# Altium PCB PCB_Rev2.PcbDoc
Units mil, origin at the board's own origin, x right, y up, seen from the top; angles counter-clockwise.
Board outline 1535 x 1720 mil, 2 copper layers (Top Layer, Bottom Layer), stack 61.2 mil thick; 17 components, 24 nets, 115 pads, 26 vias.
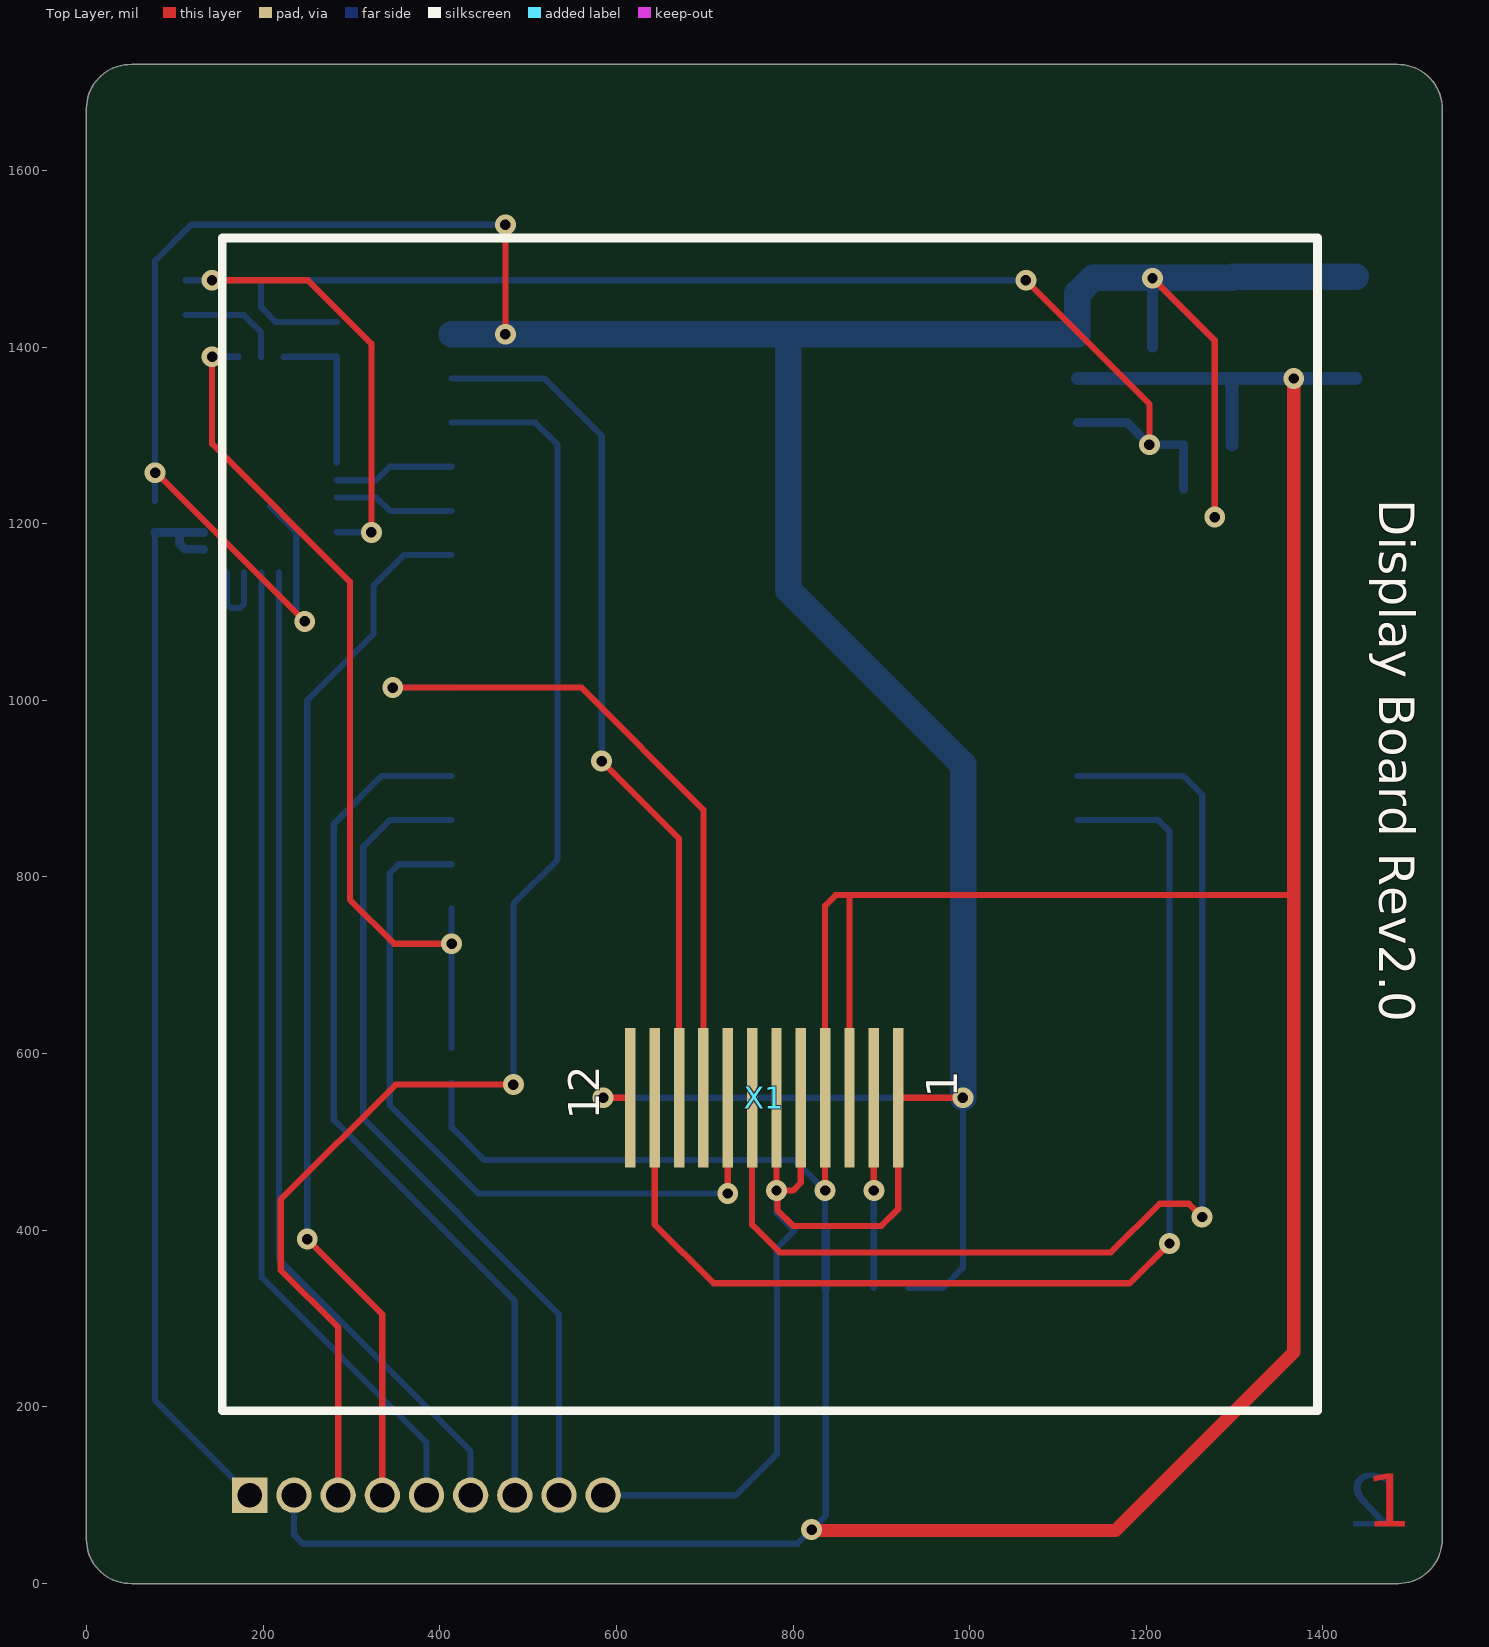
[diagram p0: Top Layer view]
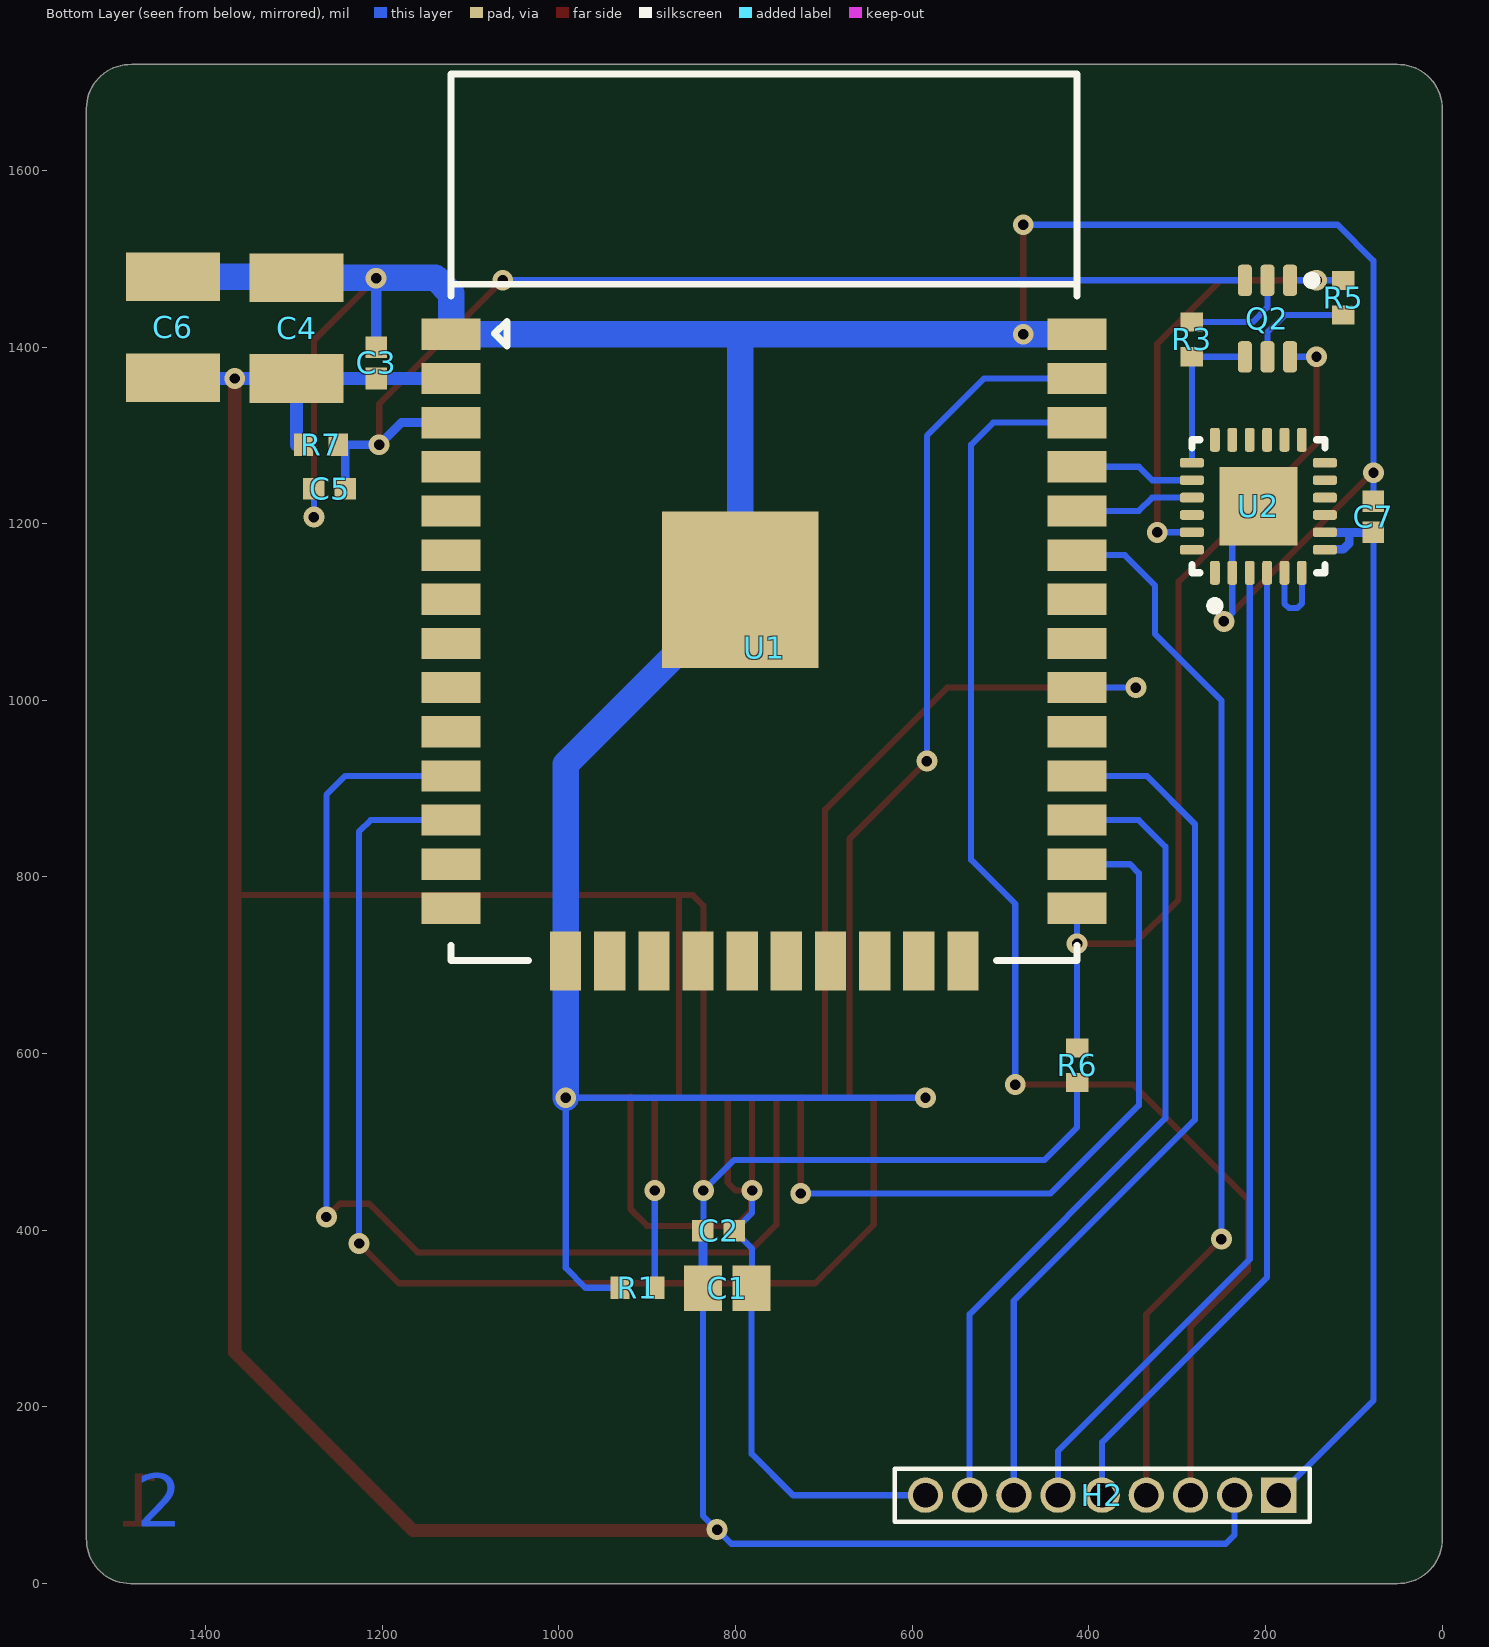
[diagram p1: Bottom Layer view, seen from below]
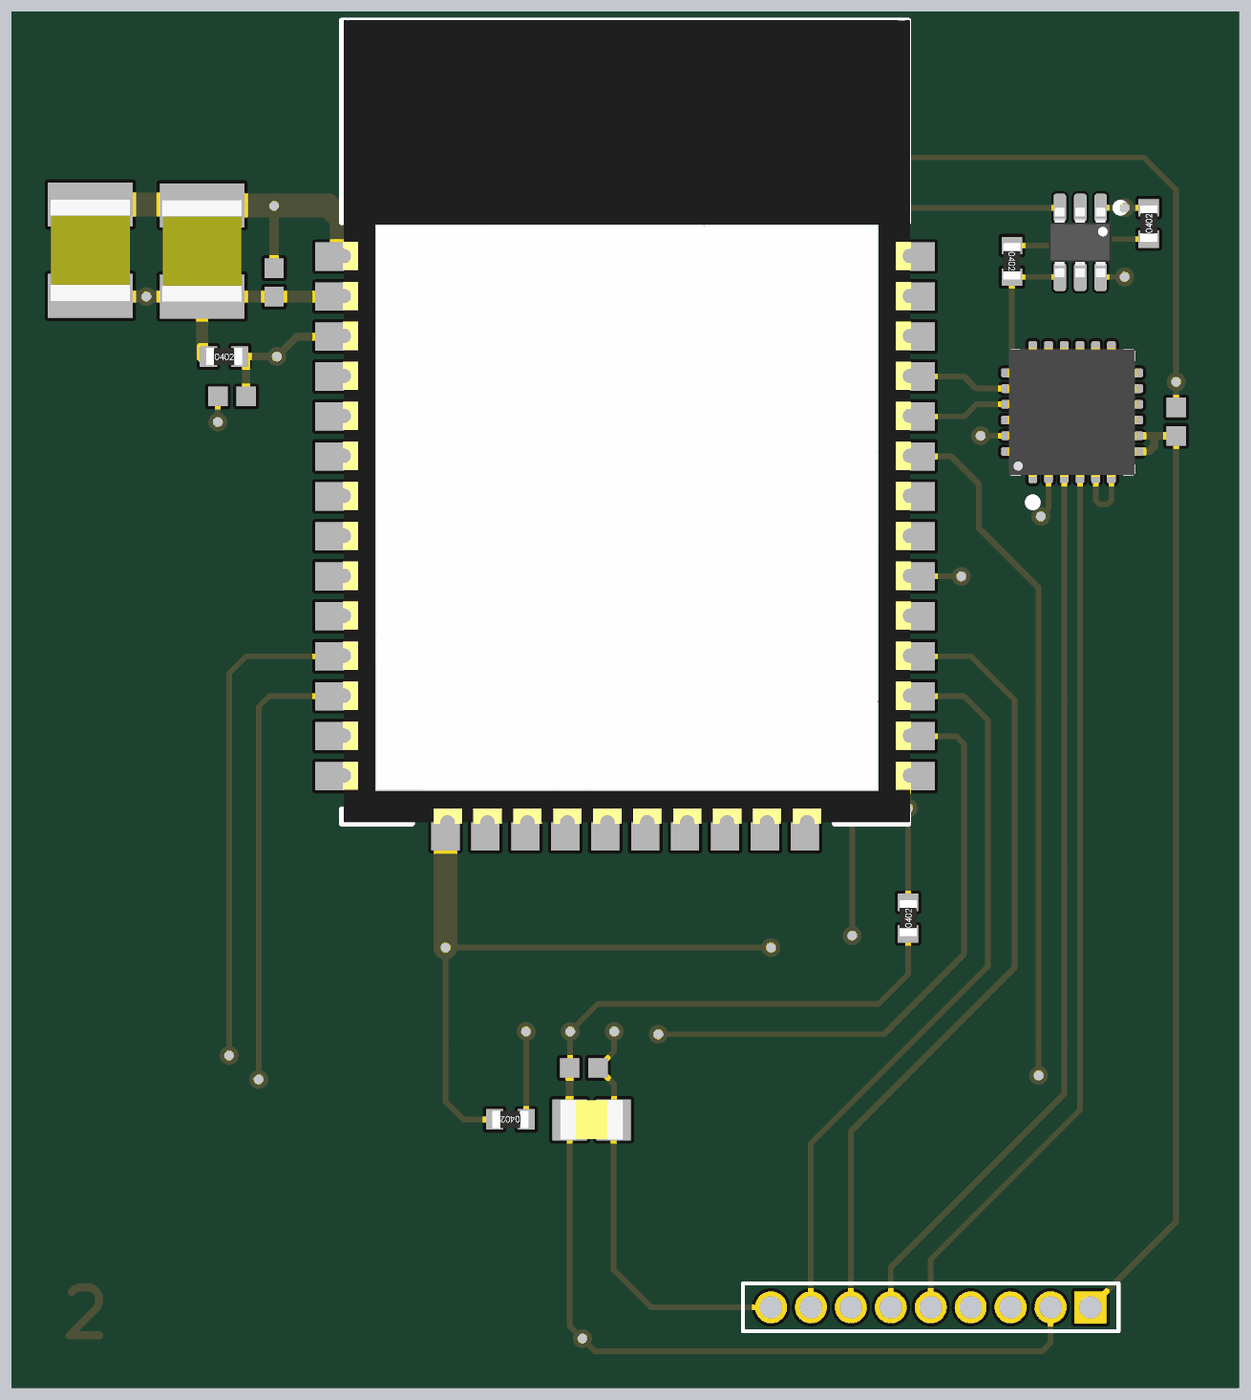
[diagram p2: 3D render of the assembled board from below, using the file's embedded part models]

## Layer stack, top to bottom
Top Solder: solder mask 0.4, Solder Resist, Dk 3.5
Top Layer: signal copper 1.4
Dielectric 1: dielectric 58.4, FR-4, Dk 4.8
Bottom Layer: signal copper 1.4
Bottom Solder: solder mask 0.4, Solder Resist, Dk 3.5

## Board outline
0,50 0,1670 cw(c50,1670) 51.04,1719.99 51.04,1720 1483.96,1720 1483.96,1719.99 cw(c1485,1670) 1535,1670 1535,51.04 1534.99,51.04 cw(c1485,50) 1485,0 51.04,0 51.04,0.01 cw(c50,50)

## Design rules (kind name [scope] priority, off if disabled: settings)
Clearance Clearance_U2 [All vs InComponent('U2')] p1: gap=6 ignorepadtopadclearanceinfootprint=FALSE
Clearance Clearance_Q2 [All vs InComponent('Q2')] p2: gap=6 ignorepadtopadclearanceinfootprint=FALSE
Clearance [All] p3: gap=10 ignorepadtopadclearanceinfootprint=FALSE except(0: Arc-Hole Track-Hole SMDPad-Hole THPad-Hole Via-Hole Fill-Hole Poly-Hole Region-Hole Text-Hole)
MinimumSolderMaskSliver [All] p1: minsoldermaskwidth=0.5
PolygonConnect [All] p1: connectstyle=Relief reliefconductorwidth=10 reliefentries=4 polygonreliefangle="90 Angle" airgapwidth=10
RoutingVias [All] p1: holewidth=28 width=50 viastyle="Through Hole" minholewidth=28 minwidth=50 maxholewidth=28 maxwidth=50
SilkToSilkClearance [All] p1: silktosilkclearance=5
SilkToSolderMaskClearance [IsPad] p1: minsilkscreentomaskgap=5 clearancetoexposedcopper=TRUE
SolderMaskExpansion [All] p1: expansion=4 istentingtop=FALSE
Width [All] p1: maxlimit=30 minlimit=7 preferedwidth=7
27 further rules are at their usual default settings.

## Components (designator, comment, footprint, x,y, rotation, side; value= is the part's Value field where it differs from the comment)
C1 "10uF" CAPC2012X140N 809.47,334.45 r180 bottom
C2 "0.1uF" CAPC1005X56N 819.31,399.45 r180 bottom
C3 "0.1uF" CAPC1005X56N 1207.03,1382.17 r90 bottom
C4 "47uF" CAPC3225X160N 1297.03,1421.54 r90 bottom
C5 "0.1uF" CAPC1005X56N 1259.74,1239.45 r0 bottom
C6 "47uF" CAPC3225X160N 1437.03,1422.36 r90 bottom
C7 "1uF" CAPC1005X56N 77.78,1207.95 r90 bottom
H2 "CON9" HDR9X1-50MIL 585,100 r270 bottom
Q2 "BC847S" SOT65P210X110-6N 198.76,1432.28 r270 bottom
R1 "22R" "RESC1005X40L (0402 FOOTPRINT)" 911.2,335 r0 bottom
R3 "10K" "RESC1005X40L (0402 FOOTPRINT)" 283.37,1408.66 r270 bottom
R5 "10K" "RESC1005X40L (0402 FOOTPRINT)" 112.18,1455.91 r90 bottom
R6 "10K" "RESC1005X40L (0402 FOOTPRINT)" 413.37,586.89 r90 bottom
R7 "10K" "RESC1005X40L (0402 FOOTPRINT)" 1269.59,1289.45 r180 bottom
U1 "ESP32" ESP32 789.7,1127.72 r180 bottom locked
U2 "CP2104N" 24-QFN 208.07,1219.76 r90 bottom locked
X1 "TFT_1.54\"" "TFT_GLASS 1.54 INCH" 767.5,550 r90 top locked

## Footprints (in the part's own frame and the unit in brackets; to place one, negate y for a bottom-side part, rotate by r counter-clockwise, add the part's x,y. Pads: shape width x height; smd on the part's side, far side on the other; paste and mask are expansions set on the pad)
24-QFN [mm] "24-QFN Exposed Pad (4x4)"
  rrect50% 0.69x0.28 smd: 1(-1.912,1.25) 2(-1.912,0.75) 3(-1.912,0.25) 4(-1.912,-0.25) 5(-1.912,-0.75) 6(-1.912,-1.25) 13(1.913,-1.25) 14(1.913,-0.75) 15(1.913,-0.25) 16(1.913,0.25) 17(1.913,0.75) 18(1.913,1.25)
  rrect50% 0.28x0.69 smd: 7(-1.25,-1.913) 8(-0.75,-1.913) 9(-0.25,-1.913) 10(0.25,-1.913) 11(0.75,-1.913) 12(1.25,-1.913) 19(1.25,1.913) 20(0.75,1.913) 21(0.25,1.913) 22(-0.25,1.913) 23(-0.75,1.913) 24(-1.25,1.913)
  rect 2.25x2.25 smd paste-1.3: 25(0,0)
  silkscreen extent -2.99,-1.91 1.91,1.91, body extent -2.05,-2.04 2.05,2.06, height 1.08
CAPC1005X56N [mm] "Chip Capacitor, 2-Leads, Body 1.0x0.5mm, IPC Medium Density (0402 ceramic)"
  rect 0.62x0.62 smd: 1(-0.45,0) 2(0.45,0)
  body extent -0.55,-0.3 0.55,0.3, height 0.6
CAPC2012X140N [mm] "Chip Capacitor, 2-Leads, Body 2.0x1.3mm, IPC Medium Density (0805 ceramic)"
  rect 1.1x1.3 smd: 1(-0.7,0) 2(0.7,0)
  body extent -1,-0.62 1,0.63, height 1.24
CAPC3225X160N [mm] "Chip Capacitor, 2-Leads, Body 3.2x2.5mm, IPC Medium Density, (1210)"
  rect 1.4x2.7 smd: 1(-1.45,0) 2(1.45,0)
  body extent -1.61,-1.26 1.61,1.26, height 0.62
ESP32 [mm]
  rect 1.7x0.9 smd: 1(-8.441,7.283) 2(-8.441,6.013) 3(-8.441,4.743) 4(-8.441,3.473) 5(-8.441,2.203) 6(-8.441,0.933) 7(-8.441,-0.337) 8(-8.441,-1.607) 9(-8.441,-2.877) 10(-8.441,-4.147) 11(-8.441,-5.417) 12(-8.441,-6.687) 13(-8.441,-7.957) 14(-8.441,-9.227) 25(9.559,-9.227) 26(9.559,-7.957) 27(9.559,-6.687) 28(9.559,-5.417) 29(9.559,-4.147) 30(9.559,-2.877) 31(9.559,-1.607) 32(9.559,-0.337) 33(9.559,0.933) 34(9.559,2.203) 35(9.559,3.473) 36(9.559,4.743) 37(9.559,6.013) 38(9.559,7.283)
  rect 0.9x1.7 smd: 15(-5.151,-10.737) 16(-3.881,-10.737) 17(-2.611,-10.737) 18(-1.341,-10.737) 19(-0.071,-10.737) 20(1.199,-10.737) 21(2.469,-10.737) 22(3.739,-10.737) 23(5.009,-10.737) 24(6.279,-10.737)
  rect 4.5x4.5 smd: 39(-0.121,-0.057)
  silkscreen extent -8.44,-10.73 9.56,14.77, body extent -8.42,-10.74 9.65,14.8, height 3.13
HDR9X1-50MIL [mil]
  rect 40x40 hole 28: 1(0,400)
  round 40 hole 28: 2(0,350) 3(0,300) 4(0,250) 5(0,200) 6(0,150) 7(0,100) 8(0,50) 9(0,0)
  silkscreen extent -30,-35 30,435
"RESC1005X40L (0402 FOOTPRINT)" [mm] "Chip Resistor, 2-Leads, Body 1.0x0.5mm, IPC Medium Density (0402)"
  rect 0.55x0.65 smd: 1(-0.5,0) 2(0.5,0)
  body extent -0.57,-0.27 0.58,0.28, height 0.41
SOT65P210X110-6N [mm] "SC70, 6-Leads, Body 2.4x2.2mm (max), Pitch 0.65mm, IPC Medium Density"
  rrect50% 0.9x0.4 smd mask+0.076: 1(-1.1,0.675) 2(-1.1,0.025) 3(-1.1,-0.625) 4(1.1,-0.625) 5(1.1,0.025) 6(1.1,0.675)
  silkscreen extent -1.22,1.18 -0.98,1.42, body extent -1.1,-0.97 1.1,1.01, height 0.99
"TFT_GLASS 1.54 INCH" [mm] "TFT_GLASS 1.54 INCH"
  rect 4x0.3 smd: 1(0,-3.85) 2(0,-3.15) 3(0,-2.45) 4(0,-1.75) 5(0,-1.05) 6(0,-0.35) 7(0,0.35) 8(0,1.05) 9(0,1.75) 10(0,2.45) 11(0,3.15) 12(0,3.85)
  Top Layer lines w0.254: 0,-3.85 0,-3.85
  silkscreen extent -9,-15.91 24.73,15.59, body extent -9,-15.91 24.73,15.59, height 2

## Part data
C1: library part CAP_0805, "CAP 10uF 0805", LCSC_Part_Number=C307520, Manufacturer=Samsung
C2: library part CAP_0402, "CAP 0.1uF 0402", LCSC_Part_Number=C344190, Manufacturer=CCTC
C3 C5: library part CAP_0402, "CAP 0.1uF 0402", Manufacturer=Yageo, PartNumber=C60474
C4 C6: library part CAP_1210, "CAP 47uF 1210"
C7: library part CAP_0603, "CAP 1uF 16V 0402", LCSC_Part_Number=C83063, Manufacturer=Walsin
H2: "CONN HEADER 9POS .100\" PADS", PartNumber=PADS
Q2: "TRANS 2NPN 44V 0.1A SC-70-6", LCSC_Part_Number=C148112, Manufacturer=Changjiang
R1: library part RES_0402, "RES 22R 0402", LCSC_Part_Number=C25092, Manufacturer=Uniroyal
R3 R5 R6 R7: library part RES_0402, "RES 10K 0402", LCSC_Part_Number=C258091, Manufacturer=Guangdong
U1: "WIFI/Bluetooth, SMD Module", Manufacturer=Ai-Thinker
U2: "IC BRIDGE USB TO UART 24QFN", LCSC_Part_Number=C47742, Manufacturer="Silicon Labs"
X1: library part "TFT_GLASS 1.54 INCH COLOR", "1.54 INCH TFT GLASS COLOR", Manufacturer=BuyDisplay

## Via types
v1: diameter 23.62, hole 11.81, Top Layer to Bottom Layer, tented both sides, 26 vias

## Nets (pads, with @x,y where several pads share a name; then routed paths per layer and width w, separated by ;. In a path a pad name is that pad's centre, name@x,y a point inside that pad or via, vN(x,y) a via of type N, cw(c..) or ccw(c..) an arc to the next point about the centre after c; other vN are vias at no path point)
+3.3V: C1.1 C2.1 C3.1 C4.1 C6.1 H2.2 R6.1 R7.1 U1.2 X1.3 X1.4 | length 4736.6
  Top Layer w7: v1(836.4,445) X1.4 836.4,767.48 848.37,779.45 863.96,779.45 ; X1.3 863.96,779.45 ; 1367.03,779.45 863.96,779.45
  Top Layer w15: v1@830,60 1165,60 1367.03,262.03 1367.03,779.45 v1(1367.03,1364.45)
  Bottom Layer w7: H2.2 235,55 245,45 805,45 v1(821.01,61.01) 837.03,77.03 C1.1 ; R6.1 413.37,516.63 450.55,479.45 801.95,479.45 v1(836.4,445) 836.4,400.08 C2.1
  Bottom Layer w10: C1.1 C2.1 ; C4.1 C4.1@1297.15,1364.33
  Bottom Layer w15: U1.2 C3.1 C4.1 v1(1367.03,1364.45) C6.1@1437.03,1364.45 ; R7.1@1297.15,1289.45 C4.1@1297.15,1364.33
+5V: C7.1 H2.1 U2.7 U2.8 | length 1232.6
  Bottom Layer w7: C7.1 77.78,207.22 H2.1
  Bottom Layer w10: C7.1 105.28,1190.24 ; U2.7 132.26,1171.06 111.95,1171.06 105.28,1177.74 105.28,1190.24 ; U2.8 105.28,1190.24
D+: H2.6 U2.3 | length 1134.4
  Bottom Layer w7: U2.3 217.91,367.09 435,150 H2.6
D-: H2.5 U2.4 | length 1121.8
  Bottom Layer w7: U2.4 198.23,346.77 385,160 H2.5
DTR: Q2.1 R5.2 U2.23 | length 522.8
  Top Layer w7: v1(142.19,1475.59) 250.69,1475.59 322.58,1403.7 v1(322.58,1190.24)
  Bottom Layer w7: R5.2 v1(142.19,1475.59) Q2.1 ; U2.23 v1(322.58,1190.24)
EN: C5.1 Q2.3 R7.2 U1.3 | length 1264.7
  Top Layer w7: v1(1063.63,1475.59) 1203.57,1335.65 v1(1203.57,1289.45)
  Bottom Layer w7: Q2.3 v1(1063.63,1475.59)
  Bottom Layer w10: U1.3 1178.57,1314.45 v1(1203.57,1289.45) 1242.03,1289.45 C5.1
GND: C1.2 C2.2 C3.2 C4.2 C5.2 C6.2 C7.2 H2.9 R1.2 U1.1 U1.15 U1.38 U1.39 U2.2 U2.25 X1.1 X1.5 X1.6 X1.12 | length 5469.5
  Top Layer w7: v1(77.78,1257.66) 78.97,1257.66 v1(247.18,1089.45) ; v1(474.37,1414.45) v1(474.37,1538.45) ; v1(585,550) X1.12 ; X1.6 v1(781.28,445) ; X1.5 808.84,453.84 800,445 v1(781.28,445) ; v1(992.37,550) X1.1 919.07,424.07 900,405 800,405 782.31,422.69 782.31,443.97 v1(781.28,445) ; v1(1207.03,1477.87) 1277.46,1407.44 v1(1277.46,1207.46)
  Bottom Layer w7: C7.2 v1(77.78,1257.66) 77.78,1497.86 118.37,1538.45 v1(474.37,1538.45) ; U2.25 237.6,1190.24 U2.2 237.6,1099.03 v1(247.18,1089.45) ; H2.9 735,100 781.91,146.91 C1.2 781.28,335.08 781.28,379.13 C2.2 781.28,419.76 v1(781.28,445) ; v1(585,550) v1(992.37,550) 992.37,357.37 970,335 R1.2 ; v1@1206.28,1478.62 v1(1207.03,1477.87) ; v1(1277.46,1207.46) C5.2 ; C4.2 C4.2@1297.85,1479.45
  Bottom Layer w12: C3.2 v1(1207.03,1477.87)
  Bottom Layer w30: U1.38 794.47,1414.45 ; v1@992.5,550 U1.15 992.5,927.44 U1.39 794.47,1414.45 ; C4.2 1206.28,1478.62 1139.9,1478.62 1122.03,1460.75 U1.1 794.47,1414.45 ; C4.2@1297.85,1479.45 C6.2
IO0: Q2.6 R6.2 U1.25 | length 1002.6
  Top Layer w7: v1(142.3,1388.98) 142.3,1290.51 298.37,1134.45 298.37,774.45 348.37,724.45 v1(413.37,724.45)
  Bottom Layer w7: v1(142.3,1388.98) Q2.6 ; R6.2 v1(413.37,724.45) U1.25
NetQ2_2: Q2.2 R3.1 | length 123.2
  Bottom Layer w7: Q2.2 197.78,1444.86 214.29,1428.35 R3.1
NetQ2_5: Q2.5 R5.1 | length 121.3
  Bottom Layer w7: R5.1 178.13,1436.22 197.78,1416.57 Q2.5
NetR1_1: R1.1 X1.2 | length 215
  Top Layer w7: v1(891.52,445) X1.2
  Bottom Layer w7: R1.1 v1(891.52,445)
NetU2_5: U2.5 U2.6 | length 93.7
  Bottom Layer w7: U2.6 158.86,1109.63 164.04,1104.45 173.37,1104.45 178.54,1109.63 U2.5
RTS: Q2.4 R3.2 U2.19 | length 180
  Bottom Layer w7: Q2.4 R3.2 U2.19
Rx: H2.8 U1.27 | length 938.7
  Bottom Layer w7: U1.27 343.37,864.45 313.37,834.45 313.37,526.63 535,305 H2.8
RXD: U1.34 U2.21 | length 136.3
  Bottom Layer w7: U2.21 328.21,1229.61 343.37,1214.45 U1.34
SCL: H2.3 U1.36 | length 1554.7
  Top Layer w7: H2.3 285,290 220,355 220,435 350,565 v1(483.37,565)
  Bottom Layer w7: U1.36 508.37,1314.45 533.37,1289.45 533.37,819.45 483.37,769.45 v1(483.37,565)
SDA: H2.4 U1.33 | length 1198.9
  Top Layer w7: v1(250,390) 335,305 H2.4
  Bottom Layer w7: v1(250,390) 250,1000 325,1075 325,1130 359.45,1164.45 U1.33
SPI_CLK: U1.30 X1.9 | length 801.9
  Top Layer w7: v1(346.83,1014.45) 560.55,1014.45 698.6,876.4 X1.9
  Bottom Layer w7: v1(346.83,1014.45) U1.30
SPI_MOSI: U1.37 X1.10 | length 982.7
  Top Layer w7: v1(583.37,931.14) 671.04,843.46 X1.10
  Bottom Layer w7: U1.37 518.37,1364.45 583.37,1299.45 v1(583.37,931.14)
TFT_CS: U1.26 X1.8 | length 869.5
  Top Layer w7: v1(726.16,441.65) X1.8
  Bottom Layer w7: U1.26 353.37,814.45 343.37,804.45 343.37,541.63 443.35,441.65 v1(726.16,441.65)
TFT_DC: U1.11 X1.7 | length 1323.4
  Top Layer w7: X1.7 753.72,406.28 785,375 1160,375 1215,430 1248.28,430 v1(1263.28,415)
  Bottom Layer w7: U1.11 1241.83,914.45 1263.37,892.91 v1@1263.37,415
TFT_RST: U1.12 X1.11 | length 1348.6
  Top Layer w7: X1.11 643.48,406.52 710,340 1181.28,340 v1(1226.28,385)
  Bottom Layer w7: U1.12 1213.37,864.45 1226.28,851.54 v1(1226.28,385)
Tx: H2.7 U1.28 | length 1000.8
  Bottom Layer w7: U1.28 334.45,914.45 280,860 280,525 485,320 H2.7
TXD: U1.35 U2.20 | length 136.3
  Bottom Layer w7: U2.20 328.21,1249.29 343.37,1264.45 U1.35
pads on no net: U1.4 U1.5 U1.6 U1.7 U1.8 U1.9 U1.10 U1.13 U1.14 U1.16 U1.17 U1.18 U1.19 U1.20 U1.21 U1.22 U1.23 U1.24 U1.29 U1.31 U1.32 U2.1 U2.9 U2.10 U2.11 U2.12 U2.13 U2.14 U2.15 U2.16 U2.17 U2.18 U2.22 U2.24

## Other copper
Top Layer:
  text "1" at 1448.37,64.45 h60
Bottom Layer:
  text "2" at 1478.37,64.45 h60

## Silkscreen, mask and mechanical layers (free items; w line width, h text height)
Top Overlay:
  text "Display Board Rev2.0" at 1463.7,1227.45 h40 r270
Mechanical 1:
  the board outline again, w10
